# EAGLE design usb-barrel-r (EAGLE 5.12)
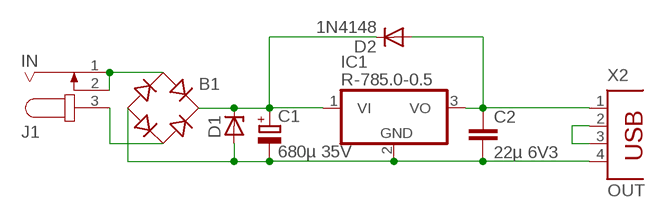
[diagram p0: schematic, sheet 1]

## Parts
B1  RECTIFIER-B40S  [B40S]
C1  680µ 35V  CPOL-EUE5-13  [E5-13]
C2  22µ 6V3  C-EUC1206  [C1206]
D1  ZENER-DIODEZD-12.5  [ZDIO12.5]
D2  1N4148  DIODE-MINIMELF  [MINIMELF]
IC1  R-785.0-0.5  7805TV  [TO220V]
J1  IN  JACK-PLUG1  [SPC4078]
X2  OUT  PN87520  [PN87520]

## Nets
+5V: C2.1 D2.A IC1.3(VO) X2.1
AC1: B1.AC2 J1.3
AC2: B1.AC1 J1.1 J1.2
D: X2.2 X2.3
GND: B1.- C1.- C2.2 D1.A IC1.2(GND) X2.4
V+: B1.+ C1.+ D1.C D2.C IC1.1(VI)

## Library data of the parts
B1 = rectifier:RECTIFIER-: Rectifier
C1 = rcl:CPOL-EU: POLARIZED CAPACITOR, European symbol
C2 = rcl:C-EU: CAPACITOR, European symbol
D1 = diode:ZENER-DIODE: Z-Diode
D2 = diode:DIODE-: DIODE
IC1 = linear:78*: Positive VOLTAGE REGULATOR Source: http://cache.national.com/ds/LM/LM78L05.pdf http://www.fairchildsemi.com/ds/LM/LM7805.pdf
J1 = con-jack:JACK-PLUG: DC POWER JACK Power Jack, DC, Right Angle, Through Hole, Rated 5A at 16VDC, PC Terminals Distributor: Farnell (www.Farnell.de) Drawing: 84N1161.pdf / 84N1162.pdf Manufacturer: SPC Technology (www.spctechnology.com) Type: SPC4077 / SPC 4078; OC_FARNELL: unknown; OC_NEWARK: unknown
X2 = con-berg:PN87520: BERG USB connector; OC_FARNELL: unknown; OC_NEWARK: unknown

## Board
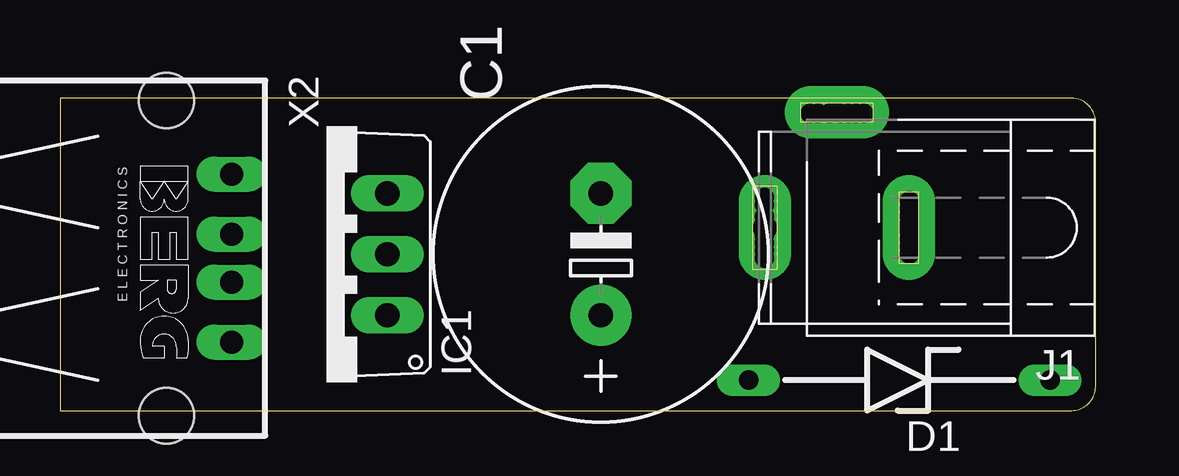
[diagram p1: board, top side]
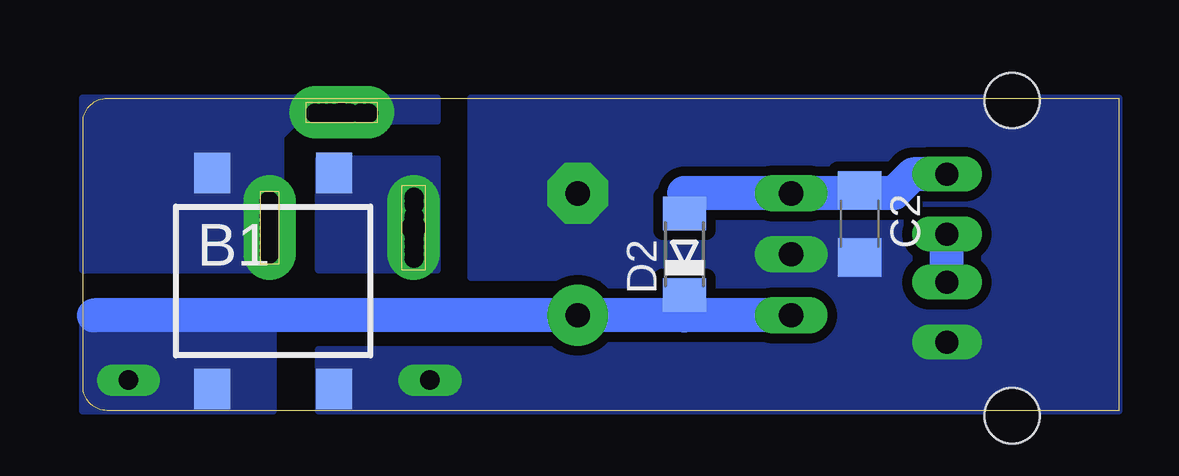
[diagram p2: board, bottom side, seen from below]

Size 43.17 x 13.01 mm. Coordinates in mm from the lower left corner, seen from the top.
Outline: 0,0 42.17,0 arc90 43.17,1 43.17,12.01 arc90 42.17,13.01 0,13.01 0,0
Copper layers (1*16): Top 0.035mm / dielectric 1.5mm / Bottom 0.035mm
Design rules "default *": minimum track width 10mil, minimum drill 24mil, track to track 16mil, track to pad 16mil, pad to pad 16mil, via to via 16mil, smd to smd 16mil, copper to edge 0mil, drill to drill 8mil, minimum pad ring 10mil, minimum via ring 8mil, stop-mask expansion 4mil, vias tented up to drill 0mil, thermal gap 10mil

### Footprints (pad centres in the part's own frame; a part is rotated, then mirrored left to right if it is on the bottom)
B40S = smd 1.5 x 1.7: + -2.55,-4.5; - 2.55,-4.5; AC1 -2.55,4.5; AC2 2.55,4.5
E5-13 = drill 1.016 pad 2.54 round: + -2.54,0 | drill 1.016 pad 2.54 octagon: - 2.54,0
C1206 = smd 1.6 x 1.8: 1 -1.4,0; 2 1.4,0
ZDIO12.5 = drill 0.813 long: A 6.223,0; C -6.35,0
MINIMELF = smd 1.4 x 1.8: A 1.7,0; C -1.7,0
TO220V = drill 1.016 long: 1 -2.54,-2.54; 2 0,-2.54; 3 2.54,-2.54
SPC4078 = drill 0.8 pad 2.184 long: 1 -3,0; 2 0,-4.8 | drill 1 pad 2.184 long: 3 3,0
PN87520 = drill 0.95 long: 1 -3.5,2.71; 2 -1,2.71; 3 1,2.71; 4 3.5,2.71 | hole 2.3: -6.57,0; 6.57,0

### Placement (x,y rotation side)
B1  35.24,5.4 0 bottom
C1  22.54,6.51 90 top
C2  10.79,7.78 270 bottom
D1  34.92,1.27 180 top
D2  18.1,6.51 90 bottom
IC1  11.11,6.51 90 top
J1  32.38,7.62 180 top
X2  4.45,6.35 270 top

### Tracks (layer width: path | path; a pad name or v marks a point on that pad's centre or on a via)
+5V
  Bottom 1.27: IC1.3
  Bottom 1.422: D2.A 18.1,9.06 IC1.3 10.67,9.06 | X2.1 8.57,9.84 9.36,9.06 10.67,9.06 | 10.67,9.06 C2.1
AC1  (via drill 0.8)
  other vias: 29.37,8.57 29.37,6.67 29.37,8.1 29.37,6.99 29.37,7.62 29.37,7.3 29.37,6.35 29.37,8.89
  pour Bottom (no thermals): 28.42,10.48 33.34,10.48 33.34,5.87 28.42,5.87
AC2  (via drill 0.8)
  other vias: 31.59,12.38 33.18,12.38 35.4,6.83 35.4,6.51 35.4,7.14 35.4,7.46 35.4,7.78 35.4,8.1 35.4,8.41 35.4,8.73 31.27,12.38 33.5,12.38 32.86,12.38 32.07,12.38 32.54,12.38
  pour Bottom (no thermals): 28.42,12.06 34.29,12.06 34.92,11.43 34.92,5.87 43.18,5.87 43.18,13.02 28.42,13.02
D
  Bottom 1.422: X2.3 X2.2
GND
  pour Bottom (no thermals): 0,13.02 26.99,13.02 26.99,5.56 21.43,5.56 21.43,2.54 33.34,2.54 33.34,0 0,0
V+
  Bottom 1.27: D2.C 18.1,3.97
  Bottom 1.422: 18.1,3.97 C1.+ | IC1.1 18.1,3.97 | 18.1,3.97 D2.C | C1.+ 42.7,3.97 | C1.+ arc-90 C1.+
  pour Bottom (no thermals): 35.24,0 43.18,0 43.18,3.97 35.24,3.97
